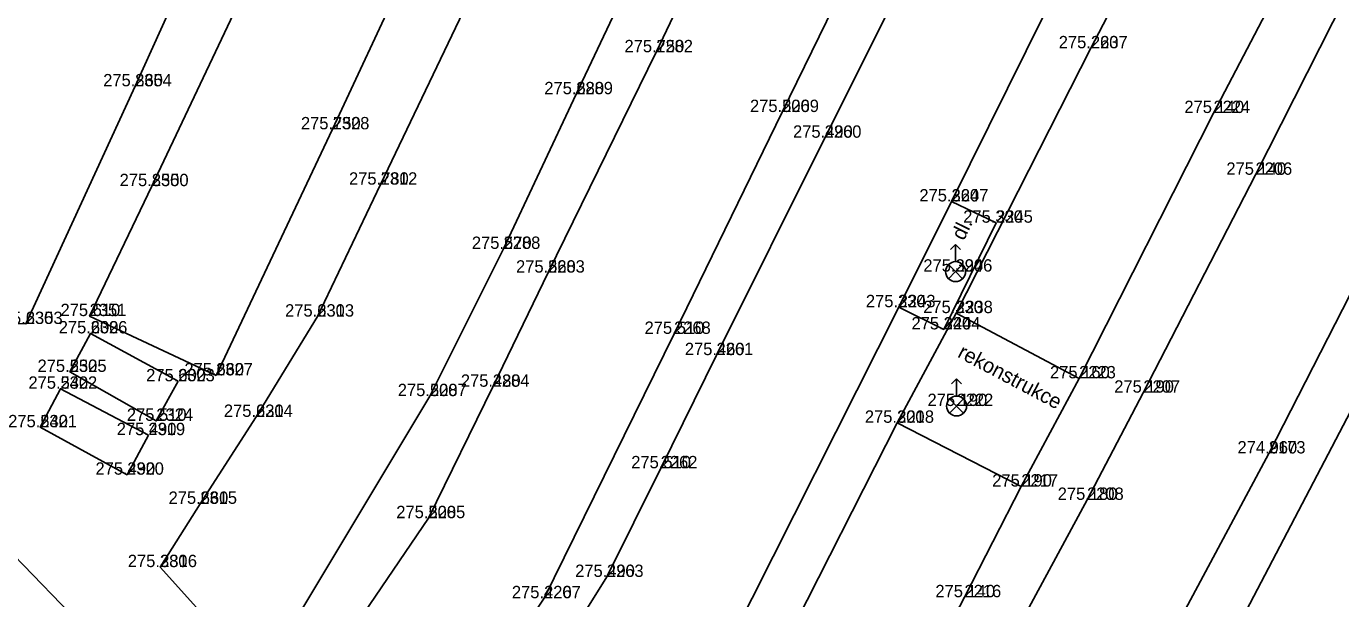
# Model space of a CAD drawing. Extents: x -776701 to -776081, y -974398 to -973771.
# Drawn here: x -776439.32 to -776412.71, y -974172.49 to -974160.9 of the extents above; entities that cross this region are included whole.
import ezdxf

# ---------------------------------------------------------------- set-up
doc = ezdxf.new("R2010")
doc.units = 0
for name, color, linetype in [('1 Body-bod', 7, 'Continuous'), ('10 Silnice-chodniky', 7, 'Continuous'), ('2 Body-cislo', 7, 'Continuous'), ('3 Body-vyska', 7, 'Continuous'), ('40 Popis-povrch', 7, 'Continuous'), ('58 Mobiliar', 7, 'Continuous'), ('7 Ploty', 7, 'Continuous')]:
    doc.layers.add(name, color=color, linetype=linetype)

msp = doc.modelspace()

# ---------------------------------------------------------------- linework, layer by layer
at = {"layer": '1 Body-bod'}
for p, q in [((-776426.57, -974161.43), (-776426.57, -974161.43)), ((-776417.77, -974161.35), (-776417.77, -974161.35)), ((-776437.12, -974162.12), (-776437.12, -974162.12)), ((-776428.19, -974162.28), (-776428.19, -974162.28)), ((-776424.02, -974162.64), (-776424.02, -974162.64)), ((-776415.29, -974162.66), (-776415.29, -974162.66)), ((-776433.12, -974162.99), (-776433.12, -974162.99)), ((-776423.16, -974163.16), (-776423.16, -974163.16)), ((-776432.15, -974164.11), (-776432.15, -974164.11)), ((-776414.44, -974163.91), (-776414.44, -974163.91)), ((-776436.78, -974164.14), (-776436.78, -974164.14)), ((-776420.59, -974164.45), (-776420.59, -974164.45)), ((-776419.69, -974164.88), (-776419.69, -974164.88)), ((-776429.66, -974165.41), (-776429.66, -974165.41)), ((-776428.76, -974165.89), (-776428.76, -974165.89)), ((-776420.51, -974165.87), (-776420.51, -974165.87)), ((-776438.04, -974166.77), (-776438.04, -974166.77)), ((-776433.43, -974166.78), (-776433.43, -974166.78)), ((-776421.66, -974166.59), (-776421.66, -974166.59)), ((-776420.5, -974166.71), (-776420.5, -974166.71)), ((-776420.75, -974167.04), (-776420.75, -974167.04)), ((-776438.02, -974167.12), (-776438.02, -974167.12)), ((-776426.21, -974167.13), (-776426.21, -974167.13)), ((-776425.35, -974167.56), (-776425.35, -974167.56)), ((-776438.44, -974167.9), (-776438.44, -974167.9)), ((-776436.25, -974168.09), (-776436.25, -974168.09)), ((-776435.48, -974167.97), (-776435.48, -974167.97)), ((-776418.01, -974168.03), (-776418.01, -974168.03)), ((-776438.63, -974168.24), (-776438.63, -974168.24)), ((-776429.88, -974168.2), (-776429.88, -974168.2)), ((-776416.71, -974168.32), (-776416.71, -974168.32)), ((-776431.15, -974168.39), (-776431.15, -974168.39)), ((-776420.49, -974168.59), (-776420.49, -974168.59)), ((-776436.69, -974168.89), (-776436.69, -974168.89)), ((-776434.67, -974168.81), (-776434.67, -974168.81)), ((-776439.04, -974169.02), (-776439.04, -974169.02)), ((-776421.69, -974168.93), (-776421.69, -974168.93)), ((-776436.85, -974169.18), (-776436.85, -974169.18)), ((-776414.17, -974169.55), (-776414.17, -974169.55)), ((-776426.48, -974169.85), (-776426.48, -974169.85)), ((-776437.28, -974169.98), (-776437.28, -974169.98)), ((-776419.18, -974170.22), (-776419.18, -974170.22)), ((-776417.85, -974170.49), (-776417.85, -974170.49)), ((-776435.8, -974170.57), (-776435.8, -974170.57)), ((-776431.18, -974170.86), (-776431.18, -974170.86)), ((-776436.61, -974171.85), (-776436.61, -974171.85)), ((-776427.57, -974172.05), (-776427.57, -974172.05)), ((-776428.84, -974172.48), (-776428.84, -974172.48)), ((-776420.33, -974172.46), (-776420.33, -974172.46))]:
    msp.add_line(p, q, dxfattribs=at)
at = {"layer": '10 Silnice-chodniky'}
for points in [[(-776421.66, -974166.59), (-776420.75, -974167.04), (-776419.69, -974164.88), (-776420.59, -974164.45)], [(-776421.69, -974168.93), (-776420.5, -974166.71)], [(-776419.18, -974170.22), (-776418.01, -974168.03)]]:
    msp.add_lwpolyline(points, dxfattribs=at)
at = {"layer": '58 Mobiliar'}
for p, q in [((-776420.51, -974165.32), (-776420.61, -974165.42)), ((-776420.51, -974165.669), (-776420.51, -974165.32)), ((-776420.51, -974165.32), (-776420.41, -974165.42)), ((-776420.51, -974165.87), (-776420.652, -974165.728)), ((-776420.51, -974165.87), (-776420.652, -974166.013)), ((-776420.51, -974165.87), (-776420.368, -974165.728)), ((-776420.51, -974165.87), (-776420.51, -974165.87)), ((-776420.51, -974165.87), (-776420.368, -974166.013)), ((-776420.49, -974168.04), (-776420.59, -974168.14)), ((-776420.49, -974168.389), (-776420.49, -974168.04)), ((-776420.49, -974168.04), (-776420.39, -974168.14)), ((-776420.49, -974168.59), (-776420.633, -974168.448)), ((-776420.49, -974168.59), (-776420.633, -974168.733)), ((-776420.49, -974168.59), (-776420.348, -974168.448)), ((-776420.49, -974168.59), (-776420.49, -974168.59)), ((-776420.49, -974168.59), (-776420.348, -974168.733))]:
    msp.add_line(p, q, dxfattribs=at)
for centre in [(-776420.51, -974165.87), (-776420.49, -974168.59)]:
    msp.add_circle(centre, 0.202, dxfattribs=at)
at = {"layer": '7 Ploty'}
for points in [[(-776440.88, -974166.89), (-776439.33, -974166.93), (-776437.12, -974162.12), (-776435.56, -974158.67), (-776434.03, -974155.26), (-776432.94, -974153.04), (-776430.36, -974147.33), (-776428.58, -974143.53), (-776427.15, -974140.36), (-776425.14, -974135.87), (-776422.56, -974130.08), (-776425.14, -974128.92), (-776428.71, -974136.96), (-776429.79, -974139.27), (-776432.93, -974146.23), (-776435.83, -974152.43), (-776438.66, -974158.67), (-776441.87, -974165.77), (-776440.88, -974166.89)], [(-776435.48, -974167.97), (-776433.12, -974162.99), (-776431.7, -974159.93), (-776430.86, -974158.2), (-776428.74, -974153.61), (-776428.34, -974152.77), (-776428.12, -974152.25), (-776426.6, -974149.09), (-776424.5, -974144.5), (-776422.38, -974140), (-776420.34, -974135.44), (-776418.71, -974131.96), (-776421.25, -974130.77), (-776423.92, -974136.54), (-776426.01, -974141.1), (-776428.12, -974145.63), (-776430.25, -974150.09), (-776432.34, -974154.68), (-776434.51, -974159.35), (-776436.78, -974164.14), (-776438.04, -974166.77), (-776435.48, -974167.97)], [(-776432.01, -974176.96), (-776430.15, -974174.43), (-776428.84, -974172.48), (-776426.21, -974167.13), (-776424.02, -974162.64), (-776420.72, -974155.89), (-776417.48, -974149.18), (-776414.84, -974143.58), (-776412.06, -974137.85), (-776410.96, -974135.57), (-776413.49, -974134.39), (-776415.66, -974138.85), (-776417.85, -974143.38), (-776420.08, -974148.01), (-776422.17, -974152.39), (-776424.4, -974156.87), (-776426.57, -974161.43), (-776428.76, -974165.89), (-776429.88, -974168.2), (-776431.18, -974170.86), (-776433.91, -974174.88), (-776432.01, -974176.96)], [(-776431.34, -974177.69), (-776430.36, -974178.74), (-776429.05, -974179.3), (-776425.05, -974173.32), (-776421.66, -974166.59), (-776420.59, -974164.45), (-776417.2, -974157.6), (-776414.58, -974152.44), (-776411.04, -974145.26), (-776408.67, -974140.55), (-776407.14, -974137.4), (-776409.65, -974136.23), (-776410.76, -974138.44), (-776413.59, -974144.07), (-776416.31, -974149.56), (-776419.81, -974156.48), (-776423.16, -974163.16), (-776425.35, -974167.56), (-776426.48, -974169.85), (-776427.57, -974172.05), (-776429.18, -974174.63), (-776431.34, -974177.69)], [(-776431.15, -974168.39), (-776429.66, -974165.41), (-776428.19, -974162.28), (-776425.9, -974157.45), (-776423.75, -974152.89), (-776421.33, -974147.81), (-776419.08, -974142.85), (-776416.94, -974138.29), (-776419.5, -974137.14), (-776421.61, -974141.66), (-776423.21, -974145.07), (-776425.27, -974149.44), (-776427.38, -974153.95), (-776429.62, -974158.72), (-776430.48, -974160.61), (-776432.15, -974164.11), (-776433.43, -974166.78), (-776434.67, -974168.81), (-776435.8, -974170.57), (-776436.61, -974171.85), (-776435.2, -974173.42), (-776434.19, -974173.45), (-776431.15, -974168.39)], [(-776418.01, -974168.03), (-776415.29, -974162.66), (-776413.55, -974159.33), (-776411.84, -974155.99), (-776409.48, -974151.54), (-776407.12, -974147.02), (-776405.49, -974143.66), (-776403.24, -974139.19), (-776405.79, -974138.02), (-776406.91, -974140.22), (-776409.14, -974144.68), (-776412.02, -974150.23), (-776414.31, -974154.7), (-776417.77, -974161.35), (-776420.5, -974166.71), (-776418.01, -974168.03)], [(-776415.33, -974192.73), (-776418.2, -974190.66), (-776421.23, -974188.49), (-776424.36, -974186.24), (-776427.39, -974184), (-776430.07, -974181.99), (-776432.38, -974179.43), (-776434.94, -974176.63), (-776434.87, -974176.53), (-776437.47, -974173.79), (-776440.34, -974170.82), (-776442.68, -974168.36), (-776445.15, -974165.67), (-776446.94, -974163.01), (-776451.45, -974156.97), (-776456.49, -974149.91), (-776458.27, -974147.5), (-776460.71, -974144.17), (-776461.87, -974145.07)], [(-776412.09, -974159.27), (-776414.44, -974163.91), (-776416.71, -974168.32), (-776417.85, -974170.49), (-776419.07, -974172.75), (-776416.58, -974174.05)], [(-776416.58, -974174.05), (-776414.17, -974169.55), (-776410.74, -974162.85)], [(-776411.46, -974166.68), (-776415.53, -974174.46), (-776417.33, -974177.87), (-776419.71, -974181.12), (-776422.7, -974185.2), (-776420.44, -974186.87)], [(-776436.25, -974168.09), (-776436.69, -974168.89), (-776438.44, -974167.9), (-776438.02, -974167.12), (-776436.25, -974168.09)], [(-776436.85, -974169.18), (-776437.28, -974169.98), (-776439.04, -974169.02), (-776438.63, -974168.24), (-776436.85, -974169.18)], [(-776425.32, -974179.79), (-776424.05, -974177.95), (-776423.75, -974178.18), (-776421.66, -974175.02), (-776420.33, -974172.46), (-776419.18, -974170.22), (-776421.69, -974168.93), (-776423.97, -974173.41), (-776426.2, -974176.81), (-776427.31, -974178.46), (-776425.32, -974179.79)]]:
    msp.add_lwpolyline(points, dxfattribs=at)

# ---------------------------------------------------------------- texts
at = {"layer": '2 Body-cislo'}
for s, p in [('2282', (-776426.57, -974161.43)), ('2237', (-776417.77, -974161.35)), ('2354', (-776437.12, -974162.12)), ('2289', (-776428.19, -974162.28)), ('2269', (-776424.02, -974162.64)), ('2224', (-776415.29, -974162.66)), ('2328', (-776433.12, -974162.99)), ('2260', (-776423.16, -974163.16)), ('2206', (-776414.44, -974163.91)), ('2350', (-776436.78, -974164.14)), ('2312', (-776432.15, -974164.11)), ('2247', (-776420.59, -974164.45)), ('2245', (-776419.69, -974164.88)), ('2288', (-776429.66, -974165.41)), ('2283', (-776428.76, -974165.89)), ('2246', (-776420.51, -974165.87)), ('2351', (-776438.04, -974166.77)), ('2243', (-776421.66, -974166.59)), ('2238', (-776420.5, -974166.71)), ('2353', (-776439.33, -974166.93)), ('2313', (-776433.43, -974166.78)), ('2326', (-776438.02, -974167.12)), ('2268', (-776426.21, -974167.13)), ('2244', (-776420.75, -974167.04)), ('2261', (-776425.35, -974167.56)), ('2325', (-776438.44, -974167.9)), ('2323', (-776436.25, -974168.09)), ('2327', (-776435.48, -974167.97)), ('2223', (-776418.01, -974168.03)), ('2322', (-776438.63, -974168.24)), ('2284', (-776429.88, -974168.2)), ('2207', (-776416.71, -974168.32)), ('2287', (-776431.15, -974168.39)), ('2222', (-776420.49, -974168.59)), ('2324', (-776436.69, -974168.89)), ('2314', (-776434.67, -974168.81)), ('2321', (-776439.04, -974169.02)), ('2218', (-776421.69, -974168.93)), ('2319', (-776436.85, -974169.18)), ('2173', (-776414.17, -974169.55)), ('2262', (-776426.48, -974169.85)), ('2320', (-776437.28, -974169.98)), ('2217', (-776419.18, -974170.22)), ('2208', (-776417.85, -974170.49)), ('2315', (-776435.8, -974170.57)), ('2285', (-776431.18, -974170.86)), ('2316', (-776436.61, -974171.85)), ('2263', (-776427.57, -974172.05)), ('2267', (-776428.84, -974172.48)), ('2216', (-776420.33, -974172.46))]:
    msp.add_text(s, height=0.25, dxfattribs=at).set_placement(p)
at = {"layer": '3 Body-vyska'}
for s, p in [('275.750', (-776427.212, -974161.43)), ('275.260', (-776418.422, -974161.35)), ('275.860', (-776437.765, -974162.12)), ('275.680', (-776428.835, -974162.28)), ('275.500', (-776424.672, -974162.64)), ('275.140', (-776415.879, -974162.66)), ('275.750', (-776433.762, -974162.99)), ('275.490', (-776423.801, -974163.16)), ('275.140', (-776415.029, -974163.91)), ('275.850', (-776437.432, -974164.14)), ('275.780', (-776432.789, -974164.11)), ('275.360', (-776421.243, -974164.45)), ('275.330', (-776420.356, -974164.88)), ('275.570', (-776430.302, -974165.41)), ('275.560', (-776429.408, -974165.89)), ('275.390', (-776421.163, -974165.87)), ('275.610', (-776438.629, -974166.77)), ('275.330', (-776422.326, -974166.59)), ('275.330', (-776421.166, -974166.71)), ('275.630', (-776439.983, -974166.93)), ('275.630', (-776434.083, -974166.78)), ('275.600', (-776438.665, -974167.12)), ('275.510', (-776426.806, -974167.13)), ('275.340', (-776421.403, -974167.04)), ('275.460', (-776425.991, -974167.56)), ('275.550', (-776439.094, -974167.9)), ('275.600', (-776436.895, -974168.09)), ('275.660', (-776436.121, -974167.97)), ('275.160', (-776418.599, -974168.03)), ('275.540', (-776439.278, -974168.24)), ('275.480', (-776430.525, -974168.2)), ('275.190', (-776417.299, -974168.32)), ('275.500', (-776431.802, -974168.39)), ('275.190', (-776421.079, -974168.59)), ('275.510', (-776437.286, -974168.89)), ('275.620', (-776435.322, -974168.81)), ('275.540', (-776439.688, -974169.02)), ('275.300', (-776422.347, -974168.93)), ('275.490', (-776437.491, -974169.18)), ('274.960', (-776414.804, -974169.55)), ('275.510', (-776427.076, -974169.85)), ('275.490', (-776437.921, -974169.98)), ('275.190', (-776419.769, -974170.22)), ('275.180', (-776418.443, -974170.49)), ('275.660', (-776436.441, -974170.57)), ('275.500', (-776431.832, -974170.86)), ('275.380', (-776437.267, -974171.85)), ('275.490', (-776428.211, -974172.05)), ('275.420', (-776429.492, -974172.48)), ('275.140', (-776420.919, -974172.46))]:
    msp.add_text(s, height=0.25, dxfattribs=at).set_placement(p)
at = {"layer": '40 Popis-povrch'}
for s, rotation, p in [('dl.', 63.8609, (-776420.344, -974165.257)), ('rekonstrukce', 332.071, (-776420.49, -974167.59))]:
    msp.add_text(s, height=0.3, rotation=rotation, dxfattribs=at).set_placement(p)

doc.saveas('drawing.dxf')
